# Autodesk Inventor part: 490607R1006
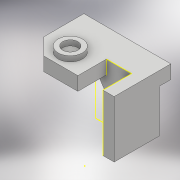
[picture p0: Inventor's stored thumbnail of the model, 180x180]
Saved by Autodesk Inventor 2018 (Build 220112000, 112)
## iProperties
Created: 2019-06
Part Number: 490607R1006
Material: 일반
Document SubType Name: Modeling
Designer: 6507_12
Density: 1 g/cm^3
Appearance: 기본값
Author: 6507_12
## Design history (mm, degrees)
sketch "스케치2"
  geometry: L1 (57.5, 98.884)-(-57.5, 98.884); L2 (-57.5, 98.884)-(-57.5, 45.884); L3 (57.5, 23.884)-(57.5, 98.884); L4 (57.5, 98.884)-(-57.5, 23.884); L5 (-57.5, 98.884)-(57.5, 23.884); L6 (-57.5, 98.884)-(-57.5, 45.884); L7 (-57.5, 45.884)-(-35.5, 23.884); L8 (57.5, 23.884)-(42.5, 23.884); L9 (42.5, 23.884)-(42.5, 61.884); L10 (42.5, 61.884)-(57.5, 61.884); L11 (-35.5, 23.884)-(9.5, 23.884); L12 (9.5, 23.884)-(9.5, 61.884); L13 (9.5, 61.884)-(42.5, 61.884); L14 (-35.5, 23.884)-(9.5, 23.884); L15 (42.5, 23.884)-(57.5, 23.884); L16 (57.5, 61.884)-(57.5, 83.884); L17 (57.5, 83.884)-(32.5, 83.884); L18 (32.5, 83.884)-(32.5, 61.884); L19 (32.5, 83.884)-(-5.68, 83.884); L20 (-5.68, 83.884)-(-5.68, 61.884); L21 (-5.68, 61.884)-(32.5, 61.884); 2 further points
  constraints: 42 end point, 5 perpendicular, 3 parallel, 3 point on line, 2 horizontal, 2 midpoint, 1 collinear, 1 vertical
  dimensions: "d0" = 115 distance of L1.start L1.end; "d1" = 75 distance of L3.start L1.start; "d3" = 53 distance of L2.end L1.end; "d5" = 15 distance of L3.start L8.end; "d11" = 22 distance of L10.end L16.end; "d14" = 25 distance of L16.end L17.end; "d15" = 90 deg angle of L17 L16
extrude "돌출1" new body sketch "스케치2" distance "d16" = 75; taper "d17" = 0 deg
sketch "스케치8"
  geometry: L1 (-5.68, 61.884)-(42.5, 61.884) reference; L2 (57.5, 83.884)-(-5.68, 83.884) reference; L3 (-5.68, 83.884)-(-5.68, 61.884) reference; L4 (57.5, 98.884)-(-57.5, 98.884) reference; L5 (57.5, 23.884)-(57.5, 98.884) reference; L6 (9.5, 23.884)-(9.5, 61.884) reference; L7 (-35.5, 23.884)-(9.5, 23.884) reference; L8 (-57.5, 45.884)-(-35.5, 23.884) reference; L9 (-57.5, 98.884)-(-57.5, 45.884) reference; 1 further point
extrude "돌출2" join sketch "스케치8" distance "d18" = 18; taper "d19" = 0 deg
sketch "스케치9"
  geometry: L1 (-35.5, 23.884)-(-57.5, 45.884) reference; C1 r 16 at (-22.5, 45.884); C2 r 10 at (-22.5, 45.884); 1 further point
  constraints: 2 centre point, 1 coincident
extrude "돌출3" join sketch "스케치9" distance "d23" = 7; taper "d24" = 0 deg
sketch "스케치10"
  geometry: L1 (28.5, 45.884)-(28.5, 73.884); L2 (28.5, 73.884)-(16.5, 73.884); L3 (16.5, 73.884)-(16.5, 45.884); C1 r 16 at (22.5, 45.884) reference; C2 r 6 at (22.5, 73.884); A1 r 6 centre (22.5, 45.884) between (28.5, 45.884) and (16.5, 45.884); 1 further point
  constraints: 6 end point, 2 centre point, 2 perpendicular, 2 point on circle, 1 coincident, 1 midpoint, 1 tangent, 1 vertical
  dimensions: "d25" = 12 diameter of A1; "d26" = 28 distance of L1.start L1.end; "d27" = 12 diameter of C2
extrude "돌출4" cut sketch "스케치10" distance "d28" = 7; taper "d29" = 0 deg
sketch "스케치12"
  geometry: L1 (15.18, 75)-(15.18, 57) reference; L2 (15.18, 57)-(0, 57) reference; L3 (0, 0)-(0, 57) reference; L4 (0, 0)-(48.18, 0) reference; L5 (48.18, 0)-(48.18, 75) reference; L6 (15.18, 75)-(48.18, 75) reference; 1 further point
sketch "스케치14"
  geometry: L1 (0, -57)-(63.18, -57) reference; L2 (63.18, 0)-(0, 0) reference; L3 (0, 0)-(0, -57) reference; L4 (48.18, 0)-(63.18, 0) reference; L5 (63.18, 0)-(38.18, 0); L6 (0, 0)-(48.18, 0) reference; L7 (15.18, -57)-(0, -57) reference; L8 (38.18, 0)-(0, -57); L9 (0, -57)-(63.18, -57); 1 further point
  constraints: 6 end point, 1 collinear, 1 point on line
  dimensions: "d30" = 25 distance of L2.start L5.end
extrude "돌출5" cut sketch "스케치14" extent not by distance; stored distance "d31" = 7; taper "d32" = 0 deg
sketch "스케치15"
  geometry: L1 (0, 38)-(0, 0) reference; L2 (0, 0)-(75, 0) reference; L3 (75, 38)-(75, 0) reference; L4 (0, 38)-(75, 38) reference; 1 further point
sketch "스케치16"
  geometry: L1 (0, 38)-(0, 0) reference; L2 (0, 0)-(75, 0) reference; L3 (75, 38)-(75, 0) reference; L4 (0, 38)-(75, 38) reference; 1 further point
node "솔리드1"
